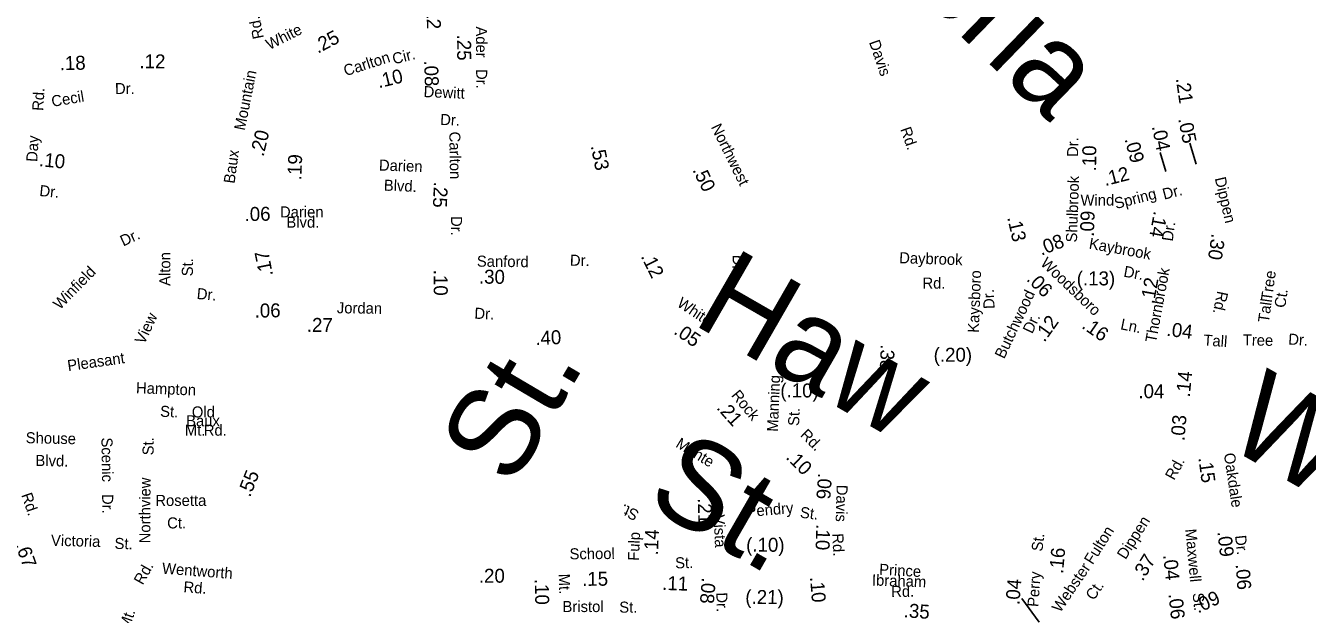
# Model space of a CAD drawing. Extents: x 1553981 to 1780076, y 812965 to 996873.
# Drawn here: x 1634131 to 1635506, y 850962 to 851594 of the extents above; entities that cross this region are included whole.
import ezdxf

# ---------------------------------------------------------------- set-up
doc = ezdxf.new("R2010")
doc.units = 0
for name, color, linetype in [('Exist Road Non-System Type 51 Label', 7, 'Continuous'), ('Exist Road Secondary Mileage Hundredths English Label', 7, 'Continuous'), ('Map Preparation Border Antique Large Shape', 7, 'Continuous')]:
    doc.layers.add(name, color=color, linetype=linetype)

msp = doc.modelspace()

# ---------------------------------------------------------------- linework, layer by layer
at = {"layer": 'Exist Road Secondary Mileage Hundredths English Label'}
for points in [[(1635380.2, 851468), (1635387.2, 851445.5)], [(1635348.4, 851457.9), (1635354.6, 851437.7)], [(1635200.1, 850979.2), (1635218.7, 850953.8)]]:
    msp.add_lwpolyline(points, dxfattribs=at)

# ---------------------------------------------------------------- texts
at = {"layer": 'Exist Road Non-System Type 51 Label'}
for s, height, rotation, p in [('Liberia', 95, 315.8274, (1634956.6, 851755.6)), ('Darien', 11.87, 358.1646, (1634509.7, 851438.7)), ('Blvd.', 11.88, 357.6287, (1634514.9, 851417.1)), ('Dr.', 11.87, 24.9788, (1634235.4, 851357)), ('Alton', 11.88, 89.7007, (1634285.8, 851314.8)), ('Haw', 95, 330.0813, (1634844.6, 851275)), ('Winfield', 11.88, 45.4764, (1634167.3, 851288.6)), ('St.', 11.88, 89.7007, (1634310.1, 851325.1)), ('Tree', 11.88, 82.0433, (1635468.3, 851298.1)), ('Dr.', 11.88, 354.7973, (1634313.9, 851300.8)), ('Ct.', 11.88, 82.0433, (1635482.7, 851290.7)), ('Tall', 11.88, 82.0433, (1635465.1, 851274.8)), ('View', 11.88, 64.9742, (1634257.9, 851251.2)), ('Tall', 11.88, 356.2177, (1635394.6, 851250.8)), ('Tree', 11.87, 359.0134, (1635437.1, 851250.9)), ('Dr.', 11.88, 356.304, (1635485.7, 851251.9)), ('Pleasant', 11.87, 8.1078, (1634176.3, 851223.2)), ('St.', 95, 59.4343, (1634652.8, 851097.3)), ('Willow', 95, 330.4395, (1635415.5, 851144.9)), ('Hampton', 11.87, 357.7266, (1634248.9, 851199.6)), ('St.', 11.87, 357.7266, (1634274.8, 851174.3)), ('Shouse', 11.88, 358.7736, (1634130.6, 851145.9)), ('Scenic', 11.88, 270.8382, (1634211.9, 851151.9)), ('St.', 11.88, 89.4677, (1634267.9, 851132.8)), ('St.', 95, 330.0813, (1634794.2, 851080.8)), ('Blvd.', 11.88, 358.7736, (1634141, 851121.5)), ('Northview', 11.88, 89.747, (1634264.4, 851038.3)), ('Dr.', 11.87, 270.287, (1634212.7, 851091.3)), ('Fulton', 11.88, 57.7894, (1635276, 851014.7)), ('Victoria', 11.88, 358.5921, (1634157.7, 851035.7)), ('St.', 11.88, 358.5921, (1634225.9, 851032.4)), ('Wentworth', 11.88, 355.6729, (1634276.7, 851005.8)), ('Prince', 11.88, 356.8554, (1635046.6, 851004.6)), ('Webster', 11.88, 55.9415, (1635241.2, 850963.2)), ('Ibraham', 11.88, 358.0191, (1635038.9, 850993.1)), ('Rd.', 11.88, 355.6729, (1634299.7, 850985.8)), ('Rd.', 11.87, 0.5004, (1635059.8, 850980.7)), ('Ct.', 11.88, 55.9415, (1635277.3, 850976.3))]:
    msp.add_text(s, height=height, rotation=rotation, dxfattribs=at).set_placement(p)
for s, p in [('Old', (1634309, 851173.5)), ('Mt.', (1634301.5, 851154)), ('Baux', (1634302.9, 851164)), ('Rd.', (1634321.8, 851153.9)), ('Rosetta', (1634269.8, 851078.5)), ('Ct.', (1634282.5, 851054.3))]:
    msp.add_text(s, height=11.88, dxfattribs=at).set_placement(p)
at = {"layer": 'Exist Road Secondary Mileage Hundredths English Label'}
for s, rotation, p in [('.12', 271.0461, (1634560.9, 851618.3)), ('.25', 27.8218, (1634444.3, 851564)), ('.25', 270.1399, (1634593.8, 851584.6)), ('.18', 1.4278, (1634167.3, 851546.4)), ('.12', 359.5405, (1634252.7, 851548.6)), ('.08', 271.8333, (1634558.3, 851556.7)), ('.10', 13.7524, (1634509.7, 851527)), ('.21', 278.3387, (1635365.2, 851537.4)), ('.20', 76.6333, (1634385.9, 851453)), ('.04', 281.2581, (1635339.5, 851486)), ('.05', 281.2581, (1635367.7, 851494.1)), ('.09', 285.178, (1635310.1, 851472.4)), ('.10', 354.3575, (1634144.5, 851443.4)), ('.19', 88.1856, (1634426.6, 851428.1)), ('.53', 281.5325, (1634737.1, 851465)), ('.10', 89.478, (1635279.7, 851437.7)), ('.12', 14.3672, (1635289.5, 851421.9)), ('.50', 296.2527, (1634846.1, 851439.3)), ('.25', 267.6101, (1634568.9, 851426.9)), ('.06', 0.8776, (1634365.7, 851384.4)), ('.13', 282.9281, (1635184.2, 851388.2)), ('.09', 88.083, (1635277.3, 851367.4)), ('.14', 259.3808, (1635341.9, 851395.7)), ('.08', 21.3748, (1635220.9, 851347.1)), ('.30', 261.1239, (1635403.9, 851371.5)), ('.17', 101.2761, (1634396.3, 851326.3)), ('.12', 296.1701, (1634790.7, 851346.6)), ('.10', 270.1885, (1634568.6, 851332.1)), ('.30', 359.2768, (1634617.1, 851317.3)), ('(.13)', 359.9134, (1635258.9, 851315.4)), ('.06', 314.5331, (1635204.2, 851321.2)), ('.12', 79.6866, (1635341.8, 851294.8)), ('.06', 0.8776, (1634376.5, 851280.7)), ('.27', 359.2391, (1634432.3, 851265.5)), ('.12', 54.5312, (1635224.2, 851253.6)), ('.16', 325.2651, (1635263.4, 851270.1)), ('.04', 352.7995, (1635354.7, 851261.3)), ('.40', 2.4289, (1634678, 851251.2)), ('.05', 325.7928, (1634825.4, 851263.9)), ('.38', 268.0143, (1635048.5, 851252.2)), ('(.20)', 359.9817, (1635105.3, 851233.4)), ('.14', 84.2957, (1635380.2, 851194.8)), ('(.10)', 359.5699, (1634940.7, 851195.2)), ('.21', 311.814, (1634871.6, 851183.4)), ('.03', 85.0866, (1635374.5, 851147.9)), ('.10', 315.4357, (1634945.8, 851129.9)), ('.15', 277.7012, (1635389.4, 851130.1)), ('.55', 68.4499, (1634371.5, 851087.2)), ('.06', 266.0405, (1634981.3, 851114)), ('.21', 271.4773, (1634852.1, 851086.7)), ('.10', 268.1601, (1634979.4, 851059)), ('.14', 87.5548, (1634809.3, 851025.3)), ('(.10)', 359.5397, (1634904, 851029.5)), ('.09', 276.2706, (1635409.9, 851050.8)), ('.67', 289.6598, (1634119.3, 851036.8)), ('.16', 84.8617, (1635244.2, 851005.3)), ('.37', 58.2734, (1635329.7, 850996.9)), ('.04', 275.9352, (1635351.7, 851025.7)), ('.06', 274.01, (1635429.5, 851015.7)), ('.20', 0.0891, (1634617.1, 850996)), ('.15', 0.5182, (1634728, 850992.6)), ('.11', 358.2675, (1634813.7, 850988.3)), ('.08', 265.4897, (1634856.6, 851001.9)), ('.10', 274.7486, (1634972.5, 851002)), ('.10', 271.247, (1634677.1, 851000)), ('(.21)', 359.5397, (1634903.1, 850973.3)), ('.04', 85.3877, (1635197.3, 850971.8)), ('.09', 25.1593, (1635389.1, 850962.8)), ('.35', 356.1567, (1635072.8, 850959)), ('.06', 275.9352, (1635357.4, 850983.9))]:
    msp.add_text(s, height=15, rotation=rotation, dxfattribs=at).set_placement(p)
msp.add_text('.04', height=15, dxfattribs=at).set_placement((1635325.1, 851194.2))
at = {"layer": 'Map Preparation Border Antique Large Shape'}
for s, height, rotation, p in [('Rd.', 11.88, 101.3696, (1634386.4, 851581.2)), ('White', 11.88, 26.8663, (1634392.3, 851567.9)), ('Ader', 11.88, 270.1399, (1634614, 851593.4)), ('Davis', 11.88, 288.8513, (1635035.8, 851576.6)), ('Cir.', 11.88, 14.0114, (1634525.9, 851552.6)), ('Carlton', 11.88, 17.7632, (1634474.1, 851539.9)), ('Mountain', 11.88, 78.7734, (1634365.8, 851481.1)), ('Dr.', 11.88, 270.1399, (1634614.2, 851547.7)), ('Rd.', 11.88, 86.4239, (1634149.4, 851502.5)), ('Cecil', 11.88, 9.4784, (1634159.3, 851507)), ('Dr.', 11.88, 0.3077, (1634226.5, 851520.8)), ('Dewitt', 11.88, 357.5789, (1634557.6, 851517.6)), ('Dr.', 11.88, 357.5789, (1634575.4, 851487.7)), ('Northwest', 11.88, 296.2528, (1634865.9, 851485.4)), ('Rd.', 11.88, 289.2176, (1635069.3, 851483.1)), ('Day', 11.88, 86.4239, (1634143, 851447.7)), ('Carlton', 11.87, 271.0461, (1634585.3, 851480.4)), ('Dr.', 11.88, 89.478, (1635260.4, 851453.2)), ('Baux', 11.88, 82.1671, (1634354.8, 851424.2)), ('Shulbrook', 11.87, 88.083, (1635259.1, 851361.3)), ('Dippen', 11.88, 283.2312, (1635407, 851430.3)), ('Dr.', 11.88, 354.3575, (1634145, 851411.4)), ('Wind', 11.88, 0.0673, (1635263, 851401)), ('Spring', 11.87, 14.3672, (1635301, 851397.3)), ('Dr.', 11.88, 14.3632, (1635352.7, 851407.3)), ('Dr.', 11.88, 270.2059, (1634587.2, 851389.8)), ('Dr.', 11.87, 81.8404, (1635361.9, 851362.2)), ('Kaybrook', 11.88, 349.7166, (1635271.4, 851354.9)), ('Sanford', 11.88, 359.2769, (1634614.9, 851335.5)), ('Dr.', 11.87, 359.2768, (1634714.8, 851336.5)), ('Dr.', 11.87, 267.7038, (1634889.8, 851348.3)), ('Daybrook', 11.87, 358.1273, (1635068.2, 851339.2)), ('Woodsboro', 11.88, 316.2259, (1635219.2, 851338)), ('Kaysboro', 11.88, 87.8518, (1635153.8, 851264.3)), ('Dr.', 11.88, 349.7166, (1635308.6, 851324.8)), ('Thornbrook', 11.87, 79.4992, (1635344, 851253.2)), ('Rd.', 11.87, 359.9817, (1635093.3, 851311.9)), ('White', 11.88, 326.4028, (1634828.9, 851293.6)), ('Dr.', 11.88, 92.4795, (1635170.8, 851290.3)), ('Butchwood', 11.88, 64.8439, (1635181, 851235.7)), ('Rd.', 11.87, 258.0244, (1635410, 851309.9)), ('Jordan', 11.88, 359.2391, (1634464.6, 851285.4)), ('Dr.', 11.88, 357.3235, (1634612.1, 851279.6)), ('Dr.', 11.88, 64.8439, (1635211.1, 851262.7)), ('Ln.', 11.88, 348.4228, (1635305.2, 851268.3)), ('Manning', 11.87, 87.6193, (1634938.1, 851158)), ('Rock', 11.88, 309.3772, (1634887.4, 851197)), ('St.', 11.87, 87.6193, (1634960.8, 851164.2)), ('Monte', 11.87, 328.5775, (1634827.5, 851142.4)), ('Rd.', 11.88, 315.4357, (1634961.3, 851153.8)), ('Rd.', 11.88, 61.2217, (1635363.5, 851105.3)), ('Oakdale', 11.88, 278.4299, (1635416.8, 851134.6)), ('Davis', 11.88, 268.4488, (1635001.2, 851101.3)), ('Rd.', 11.88, 288.9111, (1634125.7, 851090.3)), ('St.', 11.87, 155.3666, (1634790, 851072.8)), ('Vista', 11.88, 272.8289, (1634869, 851068.9)), ('Pendry', 11.88, 4.7496, (1634905, 851066.6)), ('St.', 11.87, 353.3935, (1634961.4, 851065.9)), ('Dippen', 11.88, 57.686, (1635311.3, 851020.2)), ('Fulp', 11.88, 87.5548, (1634788.9, 851019.4)), ('Rd.', 11.88, 272.603, (1634996.5, 851048.8)), ('St.', 11.88, 83.3379, (1635222, 851029.2)), ('Maxwell', 11.88, 275.3529, (1635375.4, 851053.4)), ('Dr.', 11.88, 276.2017, (1635428.8, 851046.5)), ('School', 11.88, 0.5182, (1634714.5, 851021.1)), ('Rd.', 11.88, 60.8401, (1634256.3, 850992.9)), ('St.', 11.88, 1.1753, (1634827.9, 851011.4)), ('Mt.', 11.88, 271.247, (1634702.9, 851005.6)), ('Perry', 11.87, 85.8484, (1635217.7, 850969.7)), ('Bristol', 11.88, 0.0225, (1634706.9, 850964.5)), ('St.', 11.88, 359.7824, (1634767.8, 850963.9)), ('Dr.', 11.88, 271.801, (1634871.9, 850985.5)), ('St.', 11.88, 275.9352, (1635383.2, 850984.7)), ('Mt.', 11.87, 70.4801, (1634241.3, 850944.7))]:
    msp.add_text(s, height=height, rotation=rotation, dxfattribs=at).set_placement(p)
for s, p in [('Darien', (1634403.6, 851388.3)), ('Blvd.', (1634410.5, 851377.3))]:
    msp.add_text(s, height=11.88, dxfattribs=at).set_placement(p)

doc.saveas('drawing.dxf')
